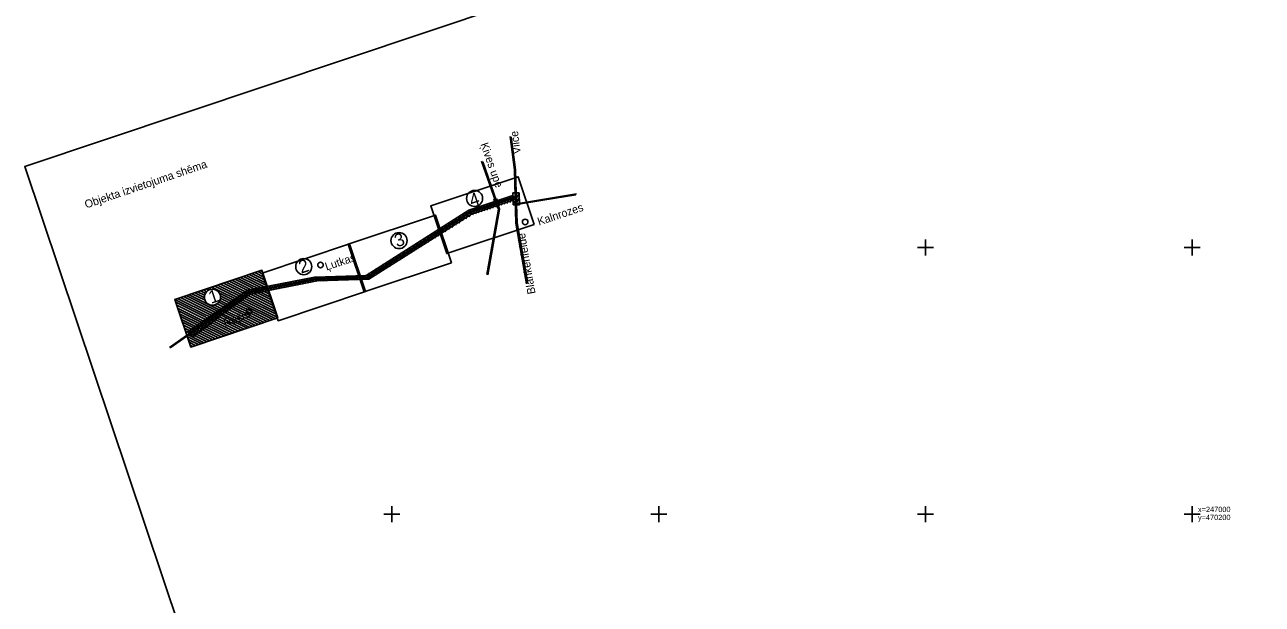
# Model space of a CAD drawing. Extents: x 469981 to 472086, y 246785 to 247785.
# Drawn here: x 469981.1 to 470213.2, y 246983.1 to 247091.8 of the extents above; entities that cross this region are included whole.
import ezdxf

# ---------------------------------------------------------------- set-up
doc = ezdxf.new("R2010")
doc.units = 0
for name, color, linetype in [('GEOD_ELEM_####_####_#', 7, 'Continuous'), ('GEOD_KORD_####_TKST_#', 7, 'Continuous'), ('RAMI_PLAN_####_TKST_#', 7, 'Continuous'), ('RELJ_NOGA_####_####_#', 7, 'Continuous'), ('RELJ_NOGL_####_####_#', 7, 'Continuous')]:
    doc.layers.add(name, color=color, linetype=linetype)

msp = doc.modelspace()

# ---------------------------------------------------------------- linework, layer by layer
at = {"layer": 'GEOD_ELEM_####_####_#'}
for p, q in [((470150, 247051.5), (470150, 247050)), ((470200, 247051.5), (470200, 247050)), ((470148.5, 247050), (470150, 247050)), ((470150, 247050), (470150, 247048.5)), ((470150, 247050), (470151.5, 247050)), ((470198.5, 247050), (470200, 247050)), ((470200, 247050), (470200, 247048.5)), ((470200, 247050), (470201.5, 247050)), ((470048.5, 247000), (470050, 247000)), ((470050, 247001.5), (470050, 247000)), ((470050, 247000), (470050, 246998.5)), ((470050, 247000), (470051.5, 247000)), ((470098.5, 247000), (470100, 247000)), ((470100, 247001.5), (470100, 247000)), ((470100, 247000), (470100, 246998.5)), ((470100, 247000), (470101.5, 247000)), ((470148.5, 247000), (470150, 247000)), ((470150, 247001.5), (470150, 247000)), ((470150, 247000), (470150, 246998.5)), ((470150, 247000), (470151.5, 247000)), ((470198.5, 247000), (470200, 247000)), ((470200, 247001.5), (470200, 247000)), ((470200, 247000), (470200, 246998.5)), ((470200, 247000), (470201.5, 247000))]:
    msp.add_line(p, q, dxfattribs=at)
at = {"layer": 'RAMI_PLAN_####_TKST_#'}
for p, q in [((470072.61, 247058.67), (470073.24, 247059.96)), ((470072.66, 247060.28), (470073.87, 247060.29)), ((470072.66, 247059.79), (470072.66, 247060.28)), ((470072.86, 247058.28), (470073.78, 247060.14)), ((470073.87, 247060.29), (470073.88, 247058.06)), ((470065.63, 247056.34), (470066.27, 247057.62)), ((470066.17, 247056.52), (470066.81, 247057.8)), ((470066.71, 247056.7), (470067.34, 247057.98)), ((470067.24, 247056.88), (470067.88, 247058.16)), ((470067.78, 247057.06), (470068.42, 247058.34)), ((470068.31, 247057.24), (470068.95, 247058.52)), ((470068.85, 247057.42), (470069.49, 247058.7)), ((470068.97, 247059.01), (470069.59, 247058.64)), ((470069.39, 247057.6), (470070.03, 247058.88)), ((470069.45, 247057.66), (470069.7, 247058.14)), ((470069.59, 247058.64), (470069.74, 247059.13)), ((470069.7, 247058.14), (470070.19, 247057.89)), ((470069.92, 247057.77), (470070.56, 247059.06)), ((470070.46, 247057.95), (470071.1, 247059.24)), ((470071, 247058.13), (470071.64, 247059.42)), ((470071.53, 247058.31), (470072.17, 247059.6)), ((470072.07, 247058.49), (470072.71, 247059.78)), ((470072.72, 247058.05), (470072.72, 247058.93)), ((470073.88, 247058.06), (470072.72, 247058.05)), ((470073.24, 247058.16), (470073.89, 247059.46)), ((470073.66, 247058.09), (470073.89, 247058.57)), ((470061.24, 247053.79), (470062.09, 247055.49)), ((470061.89, 247054.2), (470062.74, 247055.9)), ((470062.53, 247054.6), (470063.39, 247056.31)), ((470063.18, 247055), (470064.04, 247056.72)), ((470063.83, 247055.41), (470064.66, 247057.08)), ((470064.48, 247055.81), (470065.2, 247057.26)), ((470065.1, 247056.16), (470065.74, 247057.44)), ((470057.35, 247051.37), (470058.18, 247053.04)), ((470058, 247051.77), (470058.83, 247053.45)), ((470058.65, 247052.18), (470059.48, 247053.86)), ((470059.29, 247052.58), (470060.13, 247054.27)), ((470059.94, 247052.98), (470060.78, 247054.67)), ((470060.59, 247053.39), (470061.43, 247055.08)), ((470053.46, 247048.95), (470054.27, 247050.58)), ((470054.11, 247049.35), (470054.93, 247050.99)), ((470054.76, 247049.75), (470055.58, 247051.4)), ((470055.41, 247050.16), (470056.23, 247051.81)), ((470056.05, 247050.56), (470056.88, 247052.22)), ((470056.7, 247050.97), (470057.53, 247052.63)), ((470050.22, 247046.93), (470051.02, 247048.53)), ((470050.87, 247047.33), (470051.67, 247048.94)), ((470051.52, 247047.73), (470052.32, 247049.35)), ((470052.17, 247048.14), (470052.97, 247049.76)), ((470052.81, 247048.54), (470053.62, 247050.17)), ((470046.33, 247044.5), (470047.11, 247046.07)), ((470046.98, 247044.91), (470047.77, 247046.48)), ((470047.63, 247045.31), (470048.42, 247046.89)), ((470048.28, 247045.71), (470049.07, 247047.3)), ((470048.93, 247046.12), (470049.72, 247047.71)), ((470049.57, 247046.52), (470050.37, 247048.12)), ((470027.69, 247039.59), (470019.46, 247043.69)), ((470027.51, 247040.13), (470020, 247043.87)), ((470027.33, 247040.66), (470020.53, 247044.05)), ((470027.15, 247041.2), (470021.07, 247044.23)), ((470026.97, 247041.74), (470021.61, 247044.41)), ((470026.79, 247042.27), (470022.14, 247044.59)), ((470026.61, 247042.81), (470022.68, 247044.77)), ((470026.43, 247043.34), (470023.21, 247044.95)), ((470026.25, 247043.88), (470023.75, 247045.13)), ((470026.07, 247044.42), (470024.29, 247045.31)), ((470025.89, 247044.95), (470024.82, 247045.49)), ((470025.71, 247045.49), (470025.36, 247045.67)), ((470030.68, 247042.68), (470031.14, 247043.6)), ((470031.18, 247042.78), (470031.64, 247043.7)), ((470031.67, 247042.87), (470032.13, 247043.8)), ((470032.17, 247042.97), (470032.63, 247043.9)), ((470032.66, 247043.07), (470033.12, 247043.99)), ((470033.16, 247043.17), (470033.62, 247044.09)), ((470033.65, 247043.26), (470034.11, 247044.19)), ((470034.15, 247043.36), (470034.61, 247044.29)), ((470034.64, 247043.46), (470035.1, 247044.38)), ((470035.14, 247043.55), (470035.59, 247044.46)), ((470035.63, 247043.65), (470036.04, 247044.47)), ((470036.1, 247043.69), (470036.5, 247044.49)), ((470036.56, 247043.71), (470036.95, 247044.51)), ((470037.01, 247043.73), (470037.41, 247044.52)), ((470037.47, 247043.75), (470037.86, 247044.54)), ((470037.93, 247043.77), (470038.32, 247044.56)), ((470038.38, 247043.79), (470038.78, 247044.58)), ((470038.84, 247043.81), (470039.23, 247044.59)), ((470039.3, 247043.83), (470039.69, 247044.61)), ((470039.75, 247043.85), (470040.14, 247044.63)), ((470040.21, 247043.87), (470040.6, 247044.64)), ((470040.67, 247043.89), (470041.05, 247044.66)), ((470041.12, 247043.91), (470041.51, 247044.68)), ((470041.58, 247043.93), (470041.96, 247044.7)), ((470042.04, 247043.95), (470042.42, 247044.71)), ((470042.49, 247043.97), (470042.87, 247044.73)), ((470042.95, 247043.99), (470043.33, 247044.75)), ((470043.41, 247044.01), (470043.78, 247044.76)), ((470043.86, 247044.03), (470044.24, 247044.78)), ((470044.32, 247044.05), (470044.69, 247044.8)), ((470044.78, 247044.07), (470045.16, 247044.84)), ((470045.24, 247044.09), (470045.81, 247045.25)), ((470045.69, 247044.11), (470046.46, 247045.66)), ((470014.85, 247040.18), (470012.49, 247041.35)), ((470014.77, 247040.66), (470013.02, 247041.53)), ((470014.82, 247041.08), (470013.56, 247041.71)), ((470014.96, 247041.46), (470014.1, 247041.89)), ((470015.19, 247041.79), (470014.63, 247042.07)), ((470015.53, 247042.07), (470015.17, 247042.25)), ((470016.05, 247042.26), (470015.71, 247042.43)), ((470028.19, 247036.66), (470016.24, 247042.61)), ((470028.59, 247036.91), (470016.78, 247042.79)), ((470028.41, 247037.44), (470017.31, 247042.97)), ((470027.66, 247036.48), (470017.77, 247041.4)), ((470028.23, 247037.98), (470017.85, 247043.15)), ((470028.05, 247038.52), (470018.39, 247043.33)), ((470027.87, 247039.05), (470018.92, 247043.51)), ((470020.97, 247039.34), (470021.98, 247041.37)), ((470021.68, 247039.86), (470022.67, 247041.84)), ((470022.39, 247040.39), (470023.22, 247042.05)), ((470023.1, 247040.91), (470023.71, 247042.15)), ((470023.75, 247041.32), (470024.21, 247042.24)), ((470024.24, 247041.41), (470024.7, 247042.34)), ((470024.74, 247041.51), (470025.2, 247042.44)), ((470025.23, 247041.61), (470025.69, 247042.53)), ((470025.73, 247041.7), (470026.19, 247042.63)), ((470026.22, 247041.8), (470026.68, 247042.73)), ((470026.72, 247041.9), (470027.18, 247042.83)), ((470027.21, 247042), (470027.68, 247042.92)), ((470027.71, 247042.09), (470028.17, 247043.02)), ((470028.2, 247042.19), (470028.67, 247043.12)), ((470028.7, 247042.29), (470029.16, 247043.22)), ((470029.2, 247042.39), (470029.66, 247043.31)), ((470029.69, 247042.48), (470030.15, 247043.41)), ((470030.19, 247042.58), (470030.65, 247043.51)), ((470021.22, 247034.32), (470009.27, 247040.27)), ((470020.68, 247034.14), (470009.45, 247039.74)), ((470020.15, 247033.96), (470009.63, 247039.2)), ((470021.76, 247034.5), (470009.81, 247040.45)), ((470022.29, 247034.68), (470010.34, 247040.63)), ((470022.83, 247034.86), (470010.88, 247040.81)), ((470023.37, 247035.04), (470011.41, 247040.99)), ((470023.9, 247035.22), (470011.95, 247041.17)), ((470024.44, 247035.4), (470016.74, 247039.23)), ((470024.97, 247035.58), (470017.21, 247039.44)), ((470017.43, 247036.71), (470018.56, 247038.98)), ((470025.51, 247035.76), (470017.52, 247039.74)), ((470026.05, 247035.94), (470017.73, 247040.08)), ((470027.12, 247036.3), (470017.89, 247040.89)), ((470026.58, 247036.12), (470017.89, 247040.45)), ((470018.14, 247037.24), (470019.25, 247039.46)), ((470018.85, 247037.76), (470019.93, 247039.93)), ((470019.56, 247038.29), (470020.62, 247040.41)), ((470020.27, 247038.81), (470021.3, 247040.89)), ((470019.61, 247033.78), (470009.81, 247038.66)), ((470019.07, 247033.6), (470009.99, 247038.13)), ((470018.54, 247033.42), (470010.17, 247037.59)), ((470018, 247033.24), (470010.35, 247037.05)), ((470013.89, 247034.09), (470015.14, 247036.59)), ((470014.6, 247034.62), (470015.82, 247037.07)), ((470015.31, 247035.14), (470016.51, 247037.54)), ((470016.02, 247035.66), (470017.19, 247038.02)), ((470016.73, 247036.19), (470017.88, 247038.5)), ((470017.47, 247033.06), (470010.53, 247036.52)), ((470016.93, 247032.88), (470010.71, 247035.98)), ((470016.39, 247032.7), (470010.89, 247035.44)), ((470015.86, 247032.52), (470011.07, 247034.91)), ((470015.32, 247032.34), (470011.25, 247034.37)), ((470012, 247033.88), (470012.4, 247034.68)), ((470012.29, 247033.56), (470013.08, 247035.16)), ((470012.58, 247033.25), (470013.77, 247035.63)), ((470013.19, 247033.57), (470014.45, 247036.11)), ((470014.78, 247032.16), (470011.43, 247033.84)), ((470014.25, 247031.98), (470011.61, 247033.3)), ((470011.72, 247034.2), (470012.61, 247033.21)), ((470013.71, 247031.8), (470011.79, 247032.76)), ((470013.18, 247031.62), (470011.97, 247032.23)), ((470012.64, 247031.44), (470012.15, 247031.69))]:
    msp.add_line(p, q, dxfattribs=at)
for points in [[(470585.96, 246956.81), (470074.9, 246785.5), (469981.15, 247065.2), (470492.2, 247236.51)], [(470076.63, 247054.35), (470060.28, 247048.87), (470057.28, 247057.82), (470073.63, 247063.3)], [(470061.17, 247047.17), (470044.81, 247041.69), (470041.81, 247050.64), (470058.17, 247056.12)], [(470045.04, 247041.76), (470028.68, 247036.28), (470025.68, 247045.23), (470042.04, 247050.71)], [(470028.62, 247036.8), (470012.27, 247031.32), (470009.27, 247040.27), (470025.62, 247045.75)]]:
    msp.add_lwpolyline(points, close=True, dxfattribs=at)
for points in [[(470072.13, 247070.83), (470072.95, 247064.57), (470073.1, 247059.58)], [(470072.36, 247070.78), (470073.17, 247064.59), (470073.36, 247058.24)], [(470069.4, 247058.77), (470066.78, 247066.25)], [(470069.6, 247058.73), (470067.01, 247066.13)], [(470072.66, 247059.79), (470064.38, 247057.01), (470045.14, 247044.77), (470039.42, 247044.58), (470035.46, 247044.45), (470022.93, 247042), (470019.31, 247039.46), (470011.72, 247034.2)], [(470084.57, 247060.11), (470078.23, 247059.05), (470073.36, 247058.24)], [(470084.47, 247059.93), (470078.26, 247058.89), (470073.37, 247058.07)], [(470073.1, 247059.58), (470064.64, 247056.75), (470045.39, 247044.51), (470039.67, 247044.32), (470035.71, 247044.18), (470023.18, 247041.73), (470019.56, 247039.2), (470008.26, 247031.28)], [(470073.1, 247059.42), (470064.7, 247056.61), (470045.44, 247044.36), (470039.68, 247044.16), (470035.73, 247044.03), (470023.24, 247041.59), (470019.65, 247039.08), (470008.43, 247031.22)], [(470072.72, 247058.93), (470064.89, 247056.3), (470045.65, 247044.06), (470039.93, 247043.87), (470035.97, 247043.74), (470023.44, 247041.29), (470019.82, 247038.76), (470012.61, 247033.21)], [(470067.79, 247044.93), (470069.95, 247057.19), (470069.64, 247058.06)], [(470067.97, 247044.9), (470070.14, 247057.2), (470069.83, 247058.09)], [(470073.1, 247059.42), (470073.24, 247054.61), (470075.24, 247043.2)], [(470073.37, 247058.07), (470073.47, 247054.63), (470075.46, 247043.24)]]:
    msp.add_lwpolyline(points, dxfattribs=at)
for centre, radius in [((470065.49, 247059.23), 1.51), ((470074.97, 247054.82), 0.518), ((470051.32, 247051.32), 1.51), ((470033.45, 247046.43), 1.51), ((470036.59, 247046.74), 0.518), ((470016.34, 247040.69), 1.51), ((470023.21, 247038), 0.518)]:
    msp.add_circle(centre, radius, dxfattribs=at)
at = {"layer": 'RELJ_NOGA_####_####_#'}
for points in [[(470120.85, 246890.77), (470123.59, 246892.47), (470150.35, 246909.18), (470171.26, 246922.11), (470191.15, 246935.73), (470210.2, 246948.51), (470224.2, 246958.07), (470243.11, 246970.41), (470266.52, 246987.91), (470280.54, 247001.25), (470299.82, 247020.38), (470317.59, 247038.54), (470334.88, 247055.83), (470351.43, 247073.19), (470366.15, 247085.97)], [(470191.3, 246946.33), (470199.08, 246951.08), (470206.78, 246955.96), (470212.93, 246960.23), (470219.07, 246964.52), (470221.78, 246966.33), (470230.03, 246971.57), (470235.51, 246975.09), (470238.21, 246976.92), (470240.86, 246978.81), (470250.61, 246986.27), (470260.21, 246993.91), (470261.36, 246994.83)]]:
    msp.add_spline(points, degree=3, dxfattribs=at)
at = {"layer": 'RELJ_NOGL_####_####_#'}
for points in [[(470122.05, 246889.92), (470124.65, 246891.61), (470151.26, 246908.03), (470171.62, 246921.5), (470191.87, 246934.82), (470224.88, 246957.28), (470243.43, 246969.86), (470267.18, 246986.98), (470282.02, 246999.84), (470300.68, 247018.66), (470318.83, 247036.85), (470336.23, 247054.12), (470352.94, 247071.37), (470367.14, 247084.45)], [(470260.66, 246995.04), (470259.66, 246994.39), (470254.71, 246990.88), (470249.92, 246987.14), (470245.15, 246983.37), (470240.25, 246979.78), (470234.78, 246976.18), (470229.23, 246972.71), (470223.67, 246969.25), (470218.2, 246965.67), (470215.13, 246963.52), (470212.09, 246961.31), (470205.96, 246956.98), (470198.28, 246952.13), (470190.54, 246947.36)]]:
    msp.add_spline(points, degree=3, dxfattribs=at)

# ---------------------------------------------------------------- texts
at = {"layer": 'GEOD_KORD_####_TKST_#'}
for s, p in [('y=470200', (470201.11, 246998.87)), ('x=247000', (470201.11, 247000.37))]:
    msp.add_text(s, height=1, dxfattribs=at).set_placement(p)
at = {"layer": 'RAMI_PLAN_####_TKST_#'}
for s, height, rotation, p in [('Vilce', 1.5, 97.4902, (470074.16, 247067.67)), ('Ķives upe', 1.5, 289.2796, (470066.56, 247069.41)), ('Objekta izvietojuma shēma', 1.5, 18.7527, (469992.67, 247057.34)), ('4', 2.4, 18.5312, (470064.96, 247057.64)), ('Kalnrozes', 1.5, 18.5312, (470077.56, 247054.13)), ('3', 2.4, 18.5312, (470050.92, 247050.04)), ('Blankenfelde', 1.5, 99.9444, (470076.92, 247041.4)), ('Ļutkas', 1.5, 18.5312, (470037.74, 247045.68)), ('2', 2.4, 18.5312, (470032.97, 247045.1)), ('1', 2.4, 18.5312, (470016.07, 247039.43)), ('Rešņi', 1.5, 18.5312, (470018.7, 247035.14))]:
    msp.add_text(s, height=height, rotation=rotation, dxfattribs=at).set_placement(p)

doc.saveas('drawing.dxf')
